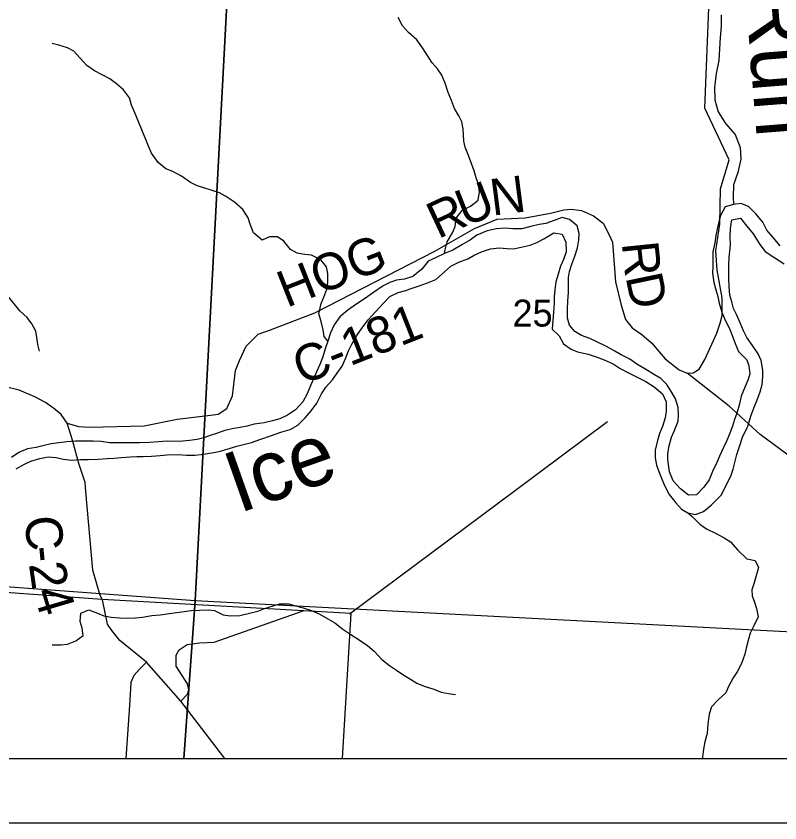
# Model space of a CAD drawing. Extents: x 0 to 34, y 0 to 22.
# Drawn here: x 4.203 to 5.391, y 14 to 15.255 of the extents above; entities that cross this region are included whole.
import ezdxf

# ---------------------------------------------------------------- set-up
doc = ezdxf.new("R2010")
doc.units = 0
for name, color, linetype in [('GM_X_City_Street', 7, 'Continuous'), ('GM_X_Corporation', 7, 'Continuous'), ('GM_X_County_Road', 7, 'Continuous'), ('GM_X_County_Road_Text', 7, 'Continuous'), ('GM_X_Major_River', 7, 'Continuous'), ('GM_X_Major_River_Text', 7, 'Continuous'), ('GM_X_Minor_River', 7, 'Continuous'), ('GM_X_Section_Text', 7, 'Continuous'), ('GM_X_Township_Road', 7, 'Continuous'), ('SH_Data', 7, 'Continuous')]:
    doc.layers.add(name, color=color, linetype=linetype)

msp = doc.modelspace()

# ---------------------------------------------------------------- linework, layer by layer
at = {"layer": 'GM_X_City_Street'}
msp.add_line((4.4563, 14.1), (4.4558, 14.1007), dxfattribs=at)
for points in [[(4.5276, 14.1), (4.5144, 14.1177), (4.4594, 14.1895), (4.4058, 14.2501), (4.3646, 14.2837), (4.3518, 14.2994), (4.3454, 14.3093), (4.3373, 14.3469)], [(4.4594, 14.1895), (4.4695, 14.2002), (4.4718, 14.2068), (4.4698, 14.2162), (4.4521, 14.2439), (4.4518, 14.2606), (4.4564, 14.2689), (4.4693, 14.2776), (4.489, 14.2802), (4.5111, 14.2812), (4.6496, 14.3297)], [(4.3744, 14.1), (4.3796, 14.1755), (4.3817, 14.2078), (4.3818, 14.2191), (4.3867, 14.2295), (4.3947, 14.239), (4.4058, 14.2501)]]:
    msp.add_lwpolyline(points, dxfattribs=at)
at = {"layer": 'GM_X_Corporation'}
for points in [[(3.3441, 14.1), (8.9, 14.1), (8.9, 20.9), (2.1, 20.9), (2.1, 16.1353), (2.1457, 16.065), (2.3447, 15.6926), (2.4297, 15.5215), (2.465, 15.4504), (2.4884, 15.4033), (2.5769, 15.2135), (2.7849, 14.8403), (2.8931, 14.6544), (3.0297, 14.4867), (3.1386, 14.3654), (3.228, 14.2415)], [(3.5455, 15.4266), (4.5353, 15.3628), (4.4813, 14.3453), (3.4851, 14.4189)], [(5.5415, 15.2956), (5.4795, 14.2928), (4.4813, 14.3453), (4.5353, 15.3628)], [(3.4676, 14.1), (4.4638, 14.1), (4.4813, 14.3453), (3.4851, 14.4189)], [(3.962, 14.1), (4.7105, 14.1), (4.7243, 14.3256), (4.337, 14.3474), (4.1144, 14.3636), (4.1184, 14.343), (4.1274, 14.3111), (4.1292, 14.294), (4.1223, 14.2823), (4.0935, 14.2756), (4.0028, 14.2813), (3.9795, 14.2362), (3.9699, 14.21), (3.9546, 14.1881), (3.9431, 14.1722), (3.9415, 14.1578)], [(4.4638, 14.1), (5.4686, 14.1), (5.4795, 14.2928), (4.4813, 14.3453)]]:
    msp.add_lwpolyline(points, close=True, dxfattribs=at)
msp.add_lwpolyline([(2.1, 19.6396), (2.1, 16.1353), (2.1457, 16.065), (2.3447, 15.6926), (2.4297, 15.5215), (2.465, 15.4504), (2.4884, 15.4033), (2.5769, 15.2135), (2.7849, 14.8403), (2.8931, 14.6544), (3.0297, 14.4867), (3.1386, 14.3654), (3.228, 14.2415), (3.3441, 14.1), (5.4627, 14.1)], dxfattribs=at)
at = {"layer": 'GM_X_County_Road'}
for points in [[(4.7424, 14.8318), (4.8541, 14.8893), (4.9157, 14.9245), (4.9514, 14.9388), (4.9948, 14.941), (5.0339, 14.9481), (5.0548, 14.9536), (5.0663, 14.9547), (5.0823, 14.9525), (5.101, 14.9443), (5.1158, 14.9327), (5.1252, 14.9146), (5.1307, 14.903), (5.1351, 14.8415), (5.1439, 14.8052), (5.151, 14.7832), (5.1609, 14.77), (5.1763, 14.7595), (5.1911, 14.7469), (5.2126, 14.7216), (5.234, 14.7045), (5.2467, 14.6996), (5.256, 14.7001), (5.2654, 14.7056), (5.2742, 14.721), (5.2929, 14.7617), (5.2978, 14.7771), (5.3011, 14.7892), (5.3011, 14.8167), (5.2934, 14.8596), (5.2912, 14.8898), (5.2973, 14.9311), (5.2983, 14.9864), (5.3122, 15.0314), (5.2739, 15.1116), (5.2892, 15.4883)], [(4.2824, 14.6216), (4.3001, 14.6164), (4.3169, 14.6153), (4.402, 14.6177), (4.4534, 14.628), (4.5054, 14.6342), (4.5171, 14.6355), (4.5307, 14.6444), (4.5397, 14.6643), (4.5444, 14.7034), (4.5506, 14.7191), (4.5609, 14.7417), (4.5797, 14.7602), (4.5989, 14.7671), (4.6674, 14.7931), (4.7424, 14.8318)], [(4.2583, 14.6471), (4.2488, 14.6537), (4.2323, 14.6626), (4.2077, 14.6729), (4.1865, 14.678), (4.1632, 14.6714), (4.1518, 14.6681), (4.1327, 14.6606), (4.1204, 14.652), (4.1121, 14.6401)], [(4.2824, 14.6216), (4.2731, 14.6352), (4.2611, 14.6451), (4.2583, 14.6471)], [(4.3115, 14.5153), (4.3102, 14.5293), (4.3006, 14.5588), (4.2909, 14.5951), (4.2824, 14.6216)], [(4.3373, 14.3469), (4.334, 14.3538), (4.3224, 14.3931), (4.3115, 14.5153)]]:
    msp.add_lwpolyline(points, dxfattribs=at)
at = {"layer": 'GM_X_Major_River'}
for points in [[(5.3911, 14.8978), (5.3805, 14.9107), (5.3703, 14.9221), (5.3643, 14.9342), (5.3533, 14.9471), (5.342, 14.9585), (5.3303, 14.9634), (5.3185, 14.9619), (5.3057, 14.9581), (5.2985, 14.9448), (5.2959, 14.9349), (5.2932, 14.9235), (5.2913, 14.9137), (5.2898, 14.9023), (5.2868, 14.8883), (5.2864, 14.8773), (5.2868, 14.8648), (5.286, 14.8549), (5.2883, 14.8405), (5.2909, 14.831), (5.2943, 14.8185), (5.2966, 14.8083), (5.3004, 14.7942), (5.3057, 14.7817), (5.3125, 14.7689), (5.3159, 14.7594), (5.3211, 14.7457), (5.3264, 14.7332), (5.3393, 14.7203), (5.3427, 14.7109), (5.3442, 14.698), (5.3408, 14.6885), (5.337, 14.6786), (5.3306, 14.6635), (5.3275, 14.6498), (5.3241, 14.6373), (5.3204, 14.6274), (5.317, 14.6168), (5.3128, 14.6062), (5.3083, 14.5948), (5.3033, 14.5838), (5.2969, 14.5702), (5.2928, 14.5603), (5.2859, 14.5463), (5.2807, 14.5338), (5.2727, 14.522)], [(5.2727, 14.522), (5.261, 14.5102), (5.2485, 14.5098), (5.2364, 14.5197), (5.2251, 14.5318), (5.219, 14.5462), (5.2168, 14.5652), (5.2168, 14.5747), (5.2187, 14.5864), (5.2225, 14.5997), (5.2262, 14.6092), (5.2327, 14.6247), (5.2334, 14.6342), (5.2327, 14.6463), (5.2285, 14.6596), (5.2229, 14.6695), (5.2149, 14.6816), (5.2055, 14.6911), (5.1956, 14.6971), (5.1809, 14.7062), (5.1684, 14.7134), (5.1575, 14.7214), (5.1442, 14.7278), (5.1344, 14.7335), (5.1212, 14.7411), (5.1049, 14.749), (5.0951, 14.7536), (5.0823, 14.7581), (5.0721, 14.7642), (5.0634, 14.7744), (5.0607, 14.785), (5.0603, 14.7991), (5.0611, 14.8116), (5.0622, 14.8252), (5.0622, 14.8351), (5.0622, 14.8484), (5.0638, 14.8578), (5.0672, 14.8692), (5.0721, 14.8817), (5.0762, 14.8946), (5.0781, 14.9071), (5.0789, 14.9166), (5.0755, 14.9284), (5.0634, 14.9386), (5.0521, 14.9416), (5.04, 14.9367), (5.0267, 14.9325), (5.0165, 14.9306), (5.0033, 14.9276), (4.9897, 14.9242), (4.9757, 14.9242), (4.9632, 14.9249), (4.95, 14.9241), (4.9356, 14.9207), (4.9198, 14.9139), (4.9099, 14.9071), (4.8963, 14.8991), (4.882, 14.8907), (4.8691, 14.8854), (4.8562, 14.8794), (4.8438, 14.8737), (4.8339, 14.8615), (4.82, 14.8498), (4.8071, 14.8456), (4.7946, 14.8441), (4.7844, 14.8403), (4.7738, 14.8353), (4.7587, 14.8251), (4.7451, 14.8152), (4.7315, 14.8061), (4.719, 14.7974), (4.7065, 14.7871), (4.6978, 14.7746), (4.6918, 14.7621), (4.6876, 14.7492), (4.6839, 14.7375), (4.6801, 14.725), (4.6752, 14.7128), (4.6702, 14.7018), (4.6661, 14.6916), (4.6612, 14.6813), (4.6555, 14.6673), (4.6491, 14.6548), (4.6377, 14.6423), (4.6252, 14.6339), (4.6131, 14.6286), (4.6018, 14.6252), (4.5886, 14.6222), (4.5731, 14.6199), (4.5625, 14.6172), (4.5515, 14.6149), (4.5417, 14.6134), (4.5277, 14.6104), (4.5149, 14.6058), (4.505, 14.6024), (4.4948, 14.599), (4.4846, 14.5963), (4.4725, 14.5948), (4.4623, 14.5937), (4.448, 14.5933), (4.4381, 14.5936)], [(5.2187, 14.511), (5.2289, 14.4977), (5.2379, 14.4882), (5.2478, 14.4822), (5.2598, 14.4799), (5.2719, 14.4841), (5.284, 14.4943), (5.2995, 14.5095), (5.3075, 14.5247), (5.315, 14.5406), (5.3181, 14.5501), (5.3215, 14.5626), (5.3241, 14.5728), (5.3283, 14.5869), (5.3328, 14.6001), (5.3408, 14.6172), (5.3464, 14.6343), (5.3506, 14.6464), (5.3551, 14.6566), (5.3604, 14.6707), (5.3631, 14.682), (5.3642, 14.6938), (5.3642, 14.7044), (5.3616, 14.7192), (5.3571, 14.7294), (5.3484, 14.7423), (5.3393, 14.7548), (5.3344, 14.7655), (5.3291, 14.778), (5.3234, 14.7908), (5.3189, 14.8003), (5.3159, 14.8102), (5.3132, 14.8208), (5.3121, 14.8341), (5.3117, 14.8466), (5.3117, 14.8682), (5.3121, 14.8792), (5.3132, 14.8894), (5.314, 14.8993), (5.3136, 14.9118), (5.314, 14.9243), (5.3163, 14.938), (5.3295, 14.9406), (5.3393, 14.9281), (5.3492, 14.916), (5.3597, 14.8997), (5.368, 14.8887), (5.3828, 14.8788), (5.3975, 14.8694)], [(4.3448, 14.5667), (4.3557, 14.5674), (4.3671, 14.5682), (4.3803, 14.5694), (4.3909, 14.5697), (4.4007, 14.5701), (4.4135, 14.5705), (4.4272, 14.5713), (4.4374, 14.5724), (4.4551, 14.5728), (4.468, 14.572), (4.4808, 14.5717), (4.4907, 14.5728), (4.5005, 14.5743), (4.5103, 14.5762), (4.5209, 14.5781), (4.5345, 14.5823), (4.5462, 14.5857), (4.5568, 14.5884), (4.5689, 14.5918), (4.5836, 14.5967), (4.5984, 14.6021), (4.6146, 14.6078), (4.629, 14.6119), (4.6411, 14.6184), (4.6528, 14.6298), (4.6619, 14.6411), (4.6706, 14.6529), (4.6782, 14.6673), (4.6846, 14.6776), (4.6952, 14.6889), (4.7035, 14.7011), (4.7103, 14.7106), (4.716, 14.7235), (4.7201, 14.7341), (4.7251, 14.7447), (4.733, 14.7583), (4.7413, 14.7701), (4.7508, 14.7822), (4.7617, 14.7951), (4.7746, 14.8084), (4.7844, 14.8187), (4.7973, 14.8251), (4.8071, 14.8278), (4.8207, 14.8323), (4.8313, 14.8357), (4.8426, 14.8399), (4.8559, 14.8452), (4.8691, 14.857), (4.8789, 14.8661), (4.8918, 14.8722), (4.9058, 14.8775), (4.9156, 14.8832), (4.9266, 14.8881), (4.9409, 14.8927), (4.9545, 14.8942), (4.9666, 14.8934), (4.9768, 14.8931), (4.9885, 14.8953), (5.0025, 14.8988), (5.0131, 14.9026), (5.0237, 14.9083), (5.0392, 14.9177), (5.0524, 14.9158), (5.0581, 14.9033), (5.0585, 14.8882), (5.0543, 14.8764), (5.0498, 14.8658), (5.046, 14.8537), (5.0426, 14.8415), (5.0407, 14.829), (5.0399, 14.8184), (5.0396, 14.8089), (5.0388, 14.7945), (5.0365, 14.768), (5.0475, 14.7574), (5.0543, 14.7452), (5.066, 14.7369), (5.0762, 14.7327), (5.0925, 14.7289), (5.1049, 14.7248), (5.1178, 14.7202), (5.1318, 14.7138), (5.1423, 14.707), (5.1567, 14.6994), (5.1824, 14.6865), (5.1953, 14.6782), (5.2085, 14.6672), (5.2142, 14.6551), (5.2138, 14.6399), (5.2123, 14.63), (5.2081, 14.6164), (5.2036, 14.6058), (5.1998, 14.5929), (5.1967, 14.5796), (5.1967, 14.5678), (5.199, 14.5565), (5.2024, 14.5466), (5.2066, 14.5364), (5.2115, 14.525), (5.2187, 14.511)], [(4.4381, 14.5936), (4.4245, 14.5925), (4.4105, 14.5914), (4.395, 14.5913), (4.3837, 14.591), (4.3482, 14.5909), (4.3353, 14.5932), (4.3228, 14.5936), (4.2956, 14.5936), (4.282, 14.5928), (4.2695, 14.5909), (4.2578, 14.5894), (4.2446, 14.5863), (4.2344, 14.5841), (4.2208, 14.5818), (4.2075, 14.5761), (4.1958, 14.5685)], [(4.203, 14.5507), (4.2162, 14.5579), (4.2261, 14.5625), (4.2397, 14.567), (4.2529, 14.5693), (4.2654, 14.5682), (4.2763, 14.5659), (4.2899, 14.564), (4.3032, 14.5651), (4.3153, 14.5651), (4.3308, 14.5659), (4.3448, 14.5667)]]:
    msp.add_lwpolyline(points, dxfattribs=at)
at = {"layer": 'GM_X_Minor_River'}
for points in [[(4.8691, 14.8854), (4.8702, 14.8915), (4.8736, 14.9036), (4.8816, 14.9177), (4.8861, 14.9275), (4.8876, 14.9404), (4.8967, 14.9526), (4.9096, 14.9594), (4.9217, 14.9685), (4.9239, 14.9814), (4.922, 14.9935), (4.9186, 15.0034), (4.9152, 15.0144), (4.9118, 15.0242), (4.9066, 15.0383), (4.9013, 15.0508), (4.8994, 15.0602), (4.8986, 15.0701), (4.8983, 15.0796), (4.896, 15.0902), (4.8915, 15.0997), (4.8846, 15.111), (4.8801, 15.1236), (4.8752, 15.1361), (4.8703, 15.1505), (4.865, 15.163), (4.8582, 15.1728), (4.8499, 15.1823), (4.8408, 15.1967), (4.834, 15.2073), (4.8261, 15.2179), (4.8132, 15.2293), (4.8042, 15.2395), (4.7974, 15.2528)], [(5.2997, 15.2568), (5.2993, 15.2386), (5.2981, 15.2215), (5.297, 15.204), (5.2961, 15.1858), (5.2919, 15.1656), (5.2889, 15.1439), (5.2896, 15.1246), (5.2948, 15.1059), (5.3065, 15.0877), (5.3212, 15.0705), (5.3291, 15.0504), (5.3302, 15.0325), (5.3256, 15.0116), (5.3188, 14.9922), (5.318, 14.9732), (5.3185, 14.9619)], [(4.6876, 14.7492), (4.6823, 14.7564), (4.6808, 14.767), (4.6774, 14.7799), (4.6737, 14.7917), (4.6774, 14.8076), (4.6816, 14.8175), (4.6861, 14.8304), (4.6877, 14.8406), (4.688, 14.8543), (4.6858, 14.8649), (4.6767, 14.8759), (4.6623, 14.8831), (4.6518, 14.8842), (4.64, 14.8861), (4.6298, 14.8918), (4.6193, 14.9046), (4.6094, 14.9118), (4.597, 14.9118), (4.5856, 14.9062), (4.5724, 14.9179), (4.5671, 14.9312), (4.5637, 14.941), (4.5558, 14.9539), (4.5429, 14.9657), (4.5289, 14.9748), (4.5191, 14.9801), (4.5081, 14.9838), (4.4949, 14.9876), (4.4847, 14.9907), (4.4745, 14.996), (4.4605, 15.0058), (4.4469, 15.013), (4.436, 15.0172), (4.4239, 15.0274), (4.4137, 15.0418), (4.4091, 15.0528), (4.4046, 15.0627), (4.3985, 15.0782), (4.394, 15.0892), (4.3865, 15.107), (4.3823, 15.1165), (4.3793, 15.1279), (4.3702, 15.1404), (4.3593, 15.1495), (4.349, 15.1574), (4.3249, 15.1696), (4.3131, 15.1779), (4.3029, 15.1893), (4.2927, 15.2003), (4.2829, 15.2056), (4.2693, 15.2097), (4.2591, 15.2124)], [(4.2396, 14.7336), (4.237, 14.7439), (4.2351, 14.7552), (4.2336, 14.7647), (4.2276, 14.7761), (4.2201, 14.786), (4.2095, 14.7959), (4.2, 14.8073), (4.191, 14.818), (4.1827, 14.8282), (4.1721, 14.8359), (4.1612, 14.845), (4.1532, 14.8496)], [(5.2478, 14.4822), (5.2542, 14.4765), (5.2663, 14.4647), (5.2769, 14.4575), (5.2916, 14.4503), (5.3041, 14.4435), (5.3139, 14.4371), (5.3252, 14.4242), (5.3396, 14.4109), (5.3524, 14.4083), (5.3577, 14.3973), (5.3547, 14.3863), (5.3505, 14.3719), (5.3471, 14.3624), (5.3479, 14.3529), (5.3513, 14.3431), (5.3543, 14.3332), (5.357, 14.3203), (5.3505, 14.3067), (5.3445, 14.2953), (5.3422, 14.2858), (5.3384, 14.2718), (5.3365, 14.2623), (5.3309, 14.2479), (5.3244, 14.235), (5.318, 14.2255), (5.3108, 14.2119), (5.3067, 14.2024), (5.2949, 14.1914), (5.2843, 14.1804), (5.2809, 14.169), (5.2787, 14.1538), (5.2775, 14.139), (5.2741, 14.1258), (5.2722, 14.1148), (5.2707, 14.1023), (5.2704, 14.1)], [(4.2593, 14.277), (4.2729, 14.277), (4.2827, 14.2781), (4.2959, 14.283), (4.3073, 14.2914), (4.3058, 14.3031), (4.3024, 14.3134), (4.3039, 14.3263), (4.316, 14.3316), (4.3296, 14.3263), (4.3394, 14.3221), (4.3511, 14.3202), (4.3636, 14.3187), (4.3757, 14.3183), (4.3885, 14.3187), (4.3995, 14.3199), (4.4139, 14.3225), (4.4271, 14.3237), (4.4411, 14.3256), (4.4532, 14.3271), (4.4645, 14.3286), (4.4751, 14.3305), (4.4883, 14.3309), (4.5019, 14.3313), (4.5118, 14.3302), (4.525, 14.3237), (4.536, 14.3218), (4.5511, 14.3226), (4.5658, 14.326), (4.5791, 14.3294), (4.5893, 14.3332), (4.6029, 14.3374), (4.6127, 14.3408), (4.6271, 14.3405), (4.6376, 14.3374), (4.6494, 14.3344), (4.6607, 14.331), (4.6743, 14.3253), (4.6879, 14.3173), (4.6989, 14.3109), (4.711, 14.3011), (4.7238, 14.2931), (4.7363, 14.2848), (4.7495, 14.2757), (4.7601, 14.267), (4.7718, 14.2541), (4.7835, 14.2446), (4.796, 14.2366), (4.8058, 14.2298), (4.8164, 14.2234), (4.8262, 14.2173), (4.8376, 14.2124), (4.8527, 14.2078), (4.864, 14.2033), (4.8757, 14.201), (4.8863, 14.1999)]]:
    msp.add_lwpolyline(points, dxfattribs=at)
at = {"layer": 'GM_X_Township_Road'}
for p, q in [((4.9777, 14.5161), (5.123, 14.6242)), ((4.7213, 14.3252), (4.9777, 14.5161))]:
    msp.add_line(p, q, dxfattribs=at)
msp.add_lwpolyline([(5.4903, 14.508), (5.4895, 14.5086), (5.4821, 14.5139), (5.4548, 14.534), (5.36, 14.604), (5.3119, 14.6481), (5.2467, 14.6996)], dxfattribs=at)
at = {"layer": 'SH_Data'}
for p, q in [((2.1, 14.1), (8.9, 14.1)), ((2, 14), (9, 14))]:
    msp.add_line(p, q, dxfattribs=at)

# ---------------------------------------------------------------- texts
at = {"layer": 'GM_X_County_Road_Text'}
for s, height, rotation, p in [('U', 0.0568, 21.4135, (4.9007, 14.927)), ('N', 0.0568, 7.3193, (4.9437, 14.9443)), ('R', 0.0568, 25.076, (4.8593, 14.9076)), ('HOG', 0.05682, 21.6888, (4.6238, 14.8009)), ('R', 0.0568, 275.9196, (5.1448, 14.9019)), ('D', 0.0568, 281.7902, (5.1506, 14.8493)), ('C-181', 0.05682, 21.4891, (4.6475, 14.6807)), ('C', 0.0568, 274.7906, (4.2163, 14.4758)), ('-', 0.0568, 275.4485, (4.2202, 14.4286)), ('2', 0.0568, 277.9658, (4.2228, 14.4027)), ('4', 0.0568, 286.5129, (4.2296, 14.359))]:
    msp.add_text(s, height=height, rotation=rotation, dxfattribs=at).set_placement(p)
at = {"layer": 'GM_X_Major_River_Text'}
for s, height, rotation, p in [('Run', 0.09467, 274.4922, (5.3367, 15.2958)), ('Ice', 0.09469, 19.4824, (4.5492, 14.481))]:
    msp.add_text(s, height=height, rotation=rotation, dxfattribs=at).set_placement(p)
at = {"layer": 'GM_X_Section_Text'}
msp.add_text('25', height=0.04186, rotation=0, dxfattribs=at).set_placement((4.9751, 14.772))

doc.saveas('drawing.dxf')
